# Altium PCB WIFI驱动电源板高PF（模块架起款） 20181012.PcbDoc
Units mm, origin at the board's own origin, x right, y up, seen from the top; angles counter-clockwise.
Board outline 211.1 x 130.13 mm, 2 copper layers (Top Layer, Bottom Layer); 46 components, 31 nets, 127 pads, 47 vias.
Unrouted connection lines stored in the file: 10.
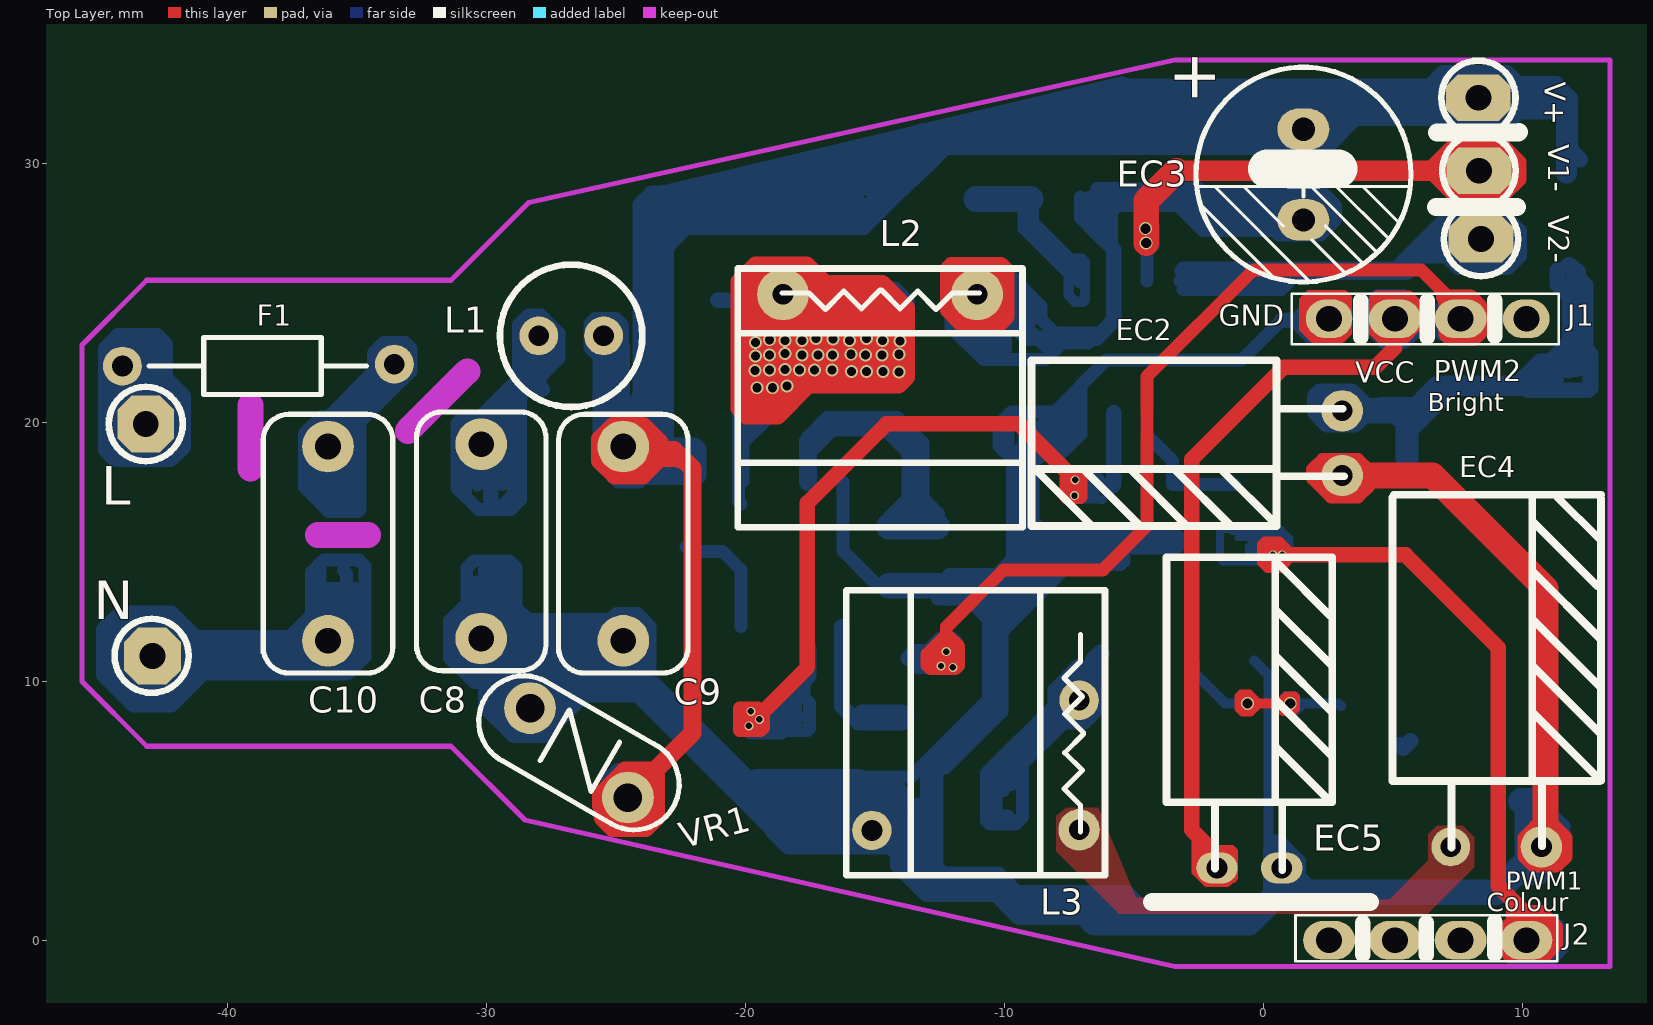
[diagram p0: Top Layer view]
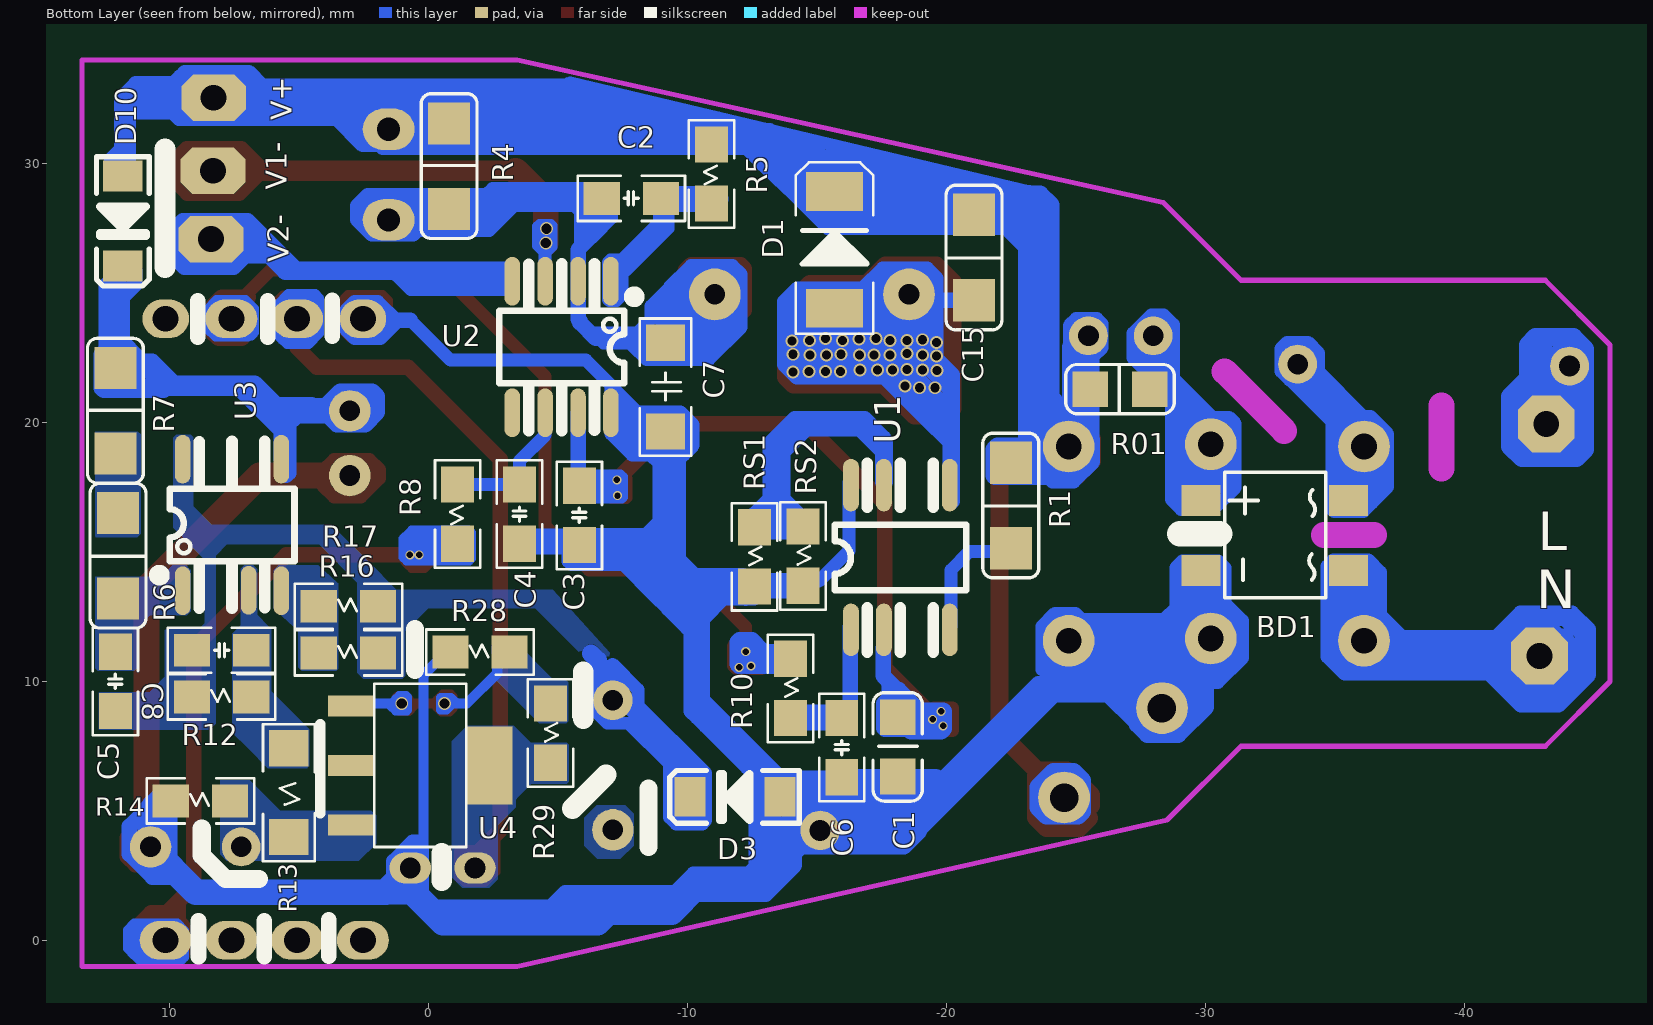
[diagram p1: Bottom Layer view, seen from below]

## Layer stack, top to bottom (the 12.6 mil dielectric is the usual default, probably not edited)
Top Solder: solder mask 0.0102, Solder Resist, Dk 3.5
Top Layer: signal copper 0.0356
Dielectric1: dielectric 0.32, FR-4, Dk 4.8
Bottom Layer: signal copper 0.0356
Bottom Solder: solder mask 0.0102, Solder Resist, Dk 3.5

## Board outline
-115.3,59.225 45.25,59.225 47.95,56.525 58.1,46.375 58.1,-51.3 38.5,-70.9 -67.65,-70.9 -123.775,-70.9 -153,-41.675 -153,21.525 -115.3,59.225

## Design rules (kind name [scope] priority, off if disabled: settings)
Clearance [All vs OnLayer('Keep-Out Layer')] p1: gap=0.4 ignorepadtopadclearanceinfootprint=FALSE except(0: Arc-Hole Track-Hole SMDPad-Hole THPad-Hole Via-Hole Fill-Hole Poly-Hole Region-Hole Text-Hole)
FabricationTestpoint [(IsPad And (OnTopLayer Or OnBottomLayer))] p1: side=3 testpointundercomponent=TRUE minsize=1.016 maxsize=2.54 preferedsize=1.524 minholesize=0 maxholesize=1.016 preferedholesize=0.813 testpointgrid=0.025 allowsidetop=TRUE allowsidebottom=TRUE usegrid=TRUE gridtolerance=0
PolygonConnect [All] p1: connectstyle=Direct reliefconductorwidth=0.254 reliefentries=4 polygonreliefangle="90 Angle" airgapwidth=0.254
RoutingVias [All] p1: holewidth=0.711 width=1.27 viastyle="Through Hole" minholewidth=0.2 minwidth=0.2 maxholewidth=1 maxwidth=1.27
SilkToSolderMaskClearance SilkscreenOverComponentPads [IsPad] p1: minsilkscreentomaskgap=0.254 clearancetoexposedcopper=TRUE
SolderMaskExpansion [All] p1: expansion=0.102
Width [All] p1: maxlimit=1 minlimit=0.2 preferedwidth=0.254 minimp=50.000000 maximp=50.000000 favimp=50.000000
28 further rules are at their usual default settings.

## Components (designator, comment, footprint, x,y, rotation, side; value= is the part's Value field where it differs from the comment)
BD1 "Comment" BD1 -31.877,15.824 r0 top
C1 "51K" C0805 -18.11,8.611 r0 bottom
C2 "Comment" C/0805(B)-new -7.823,28.651 r270 bottom
C3 "Comment" C/0805(B)-new -5.817,16.408 r0 bottom
C4 "Comment" C/0805(B)-new -3.505,16.459 r0 bottom
C5 "" C/0805(B)-new 12.1,10 r180 bottom (schematic designator C3)
C6 "Comment" C/0805(B)-new -15.951,7.442 r0 bottom
C7 "Comment" C/1206(B)-new -9.144,21.361 r180 bottom
C8 "Comment" CBB7.5-10*5 -30.201,15.405 r270 top
C8 "" C/0805(B)-new 8,11.2 r90 bottom (schematic designator C3)
C9 "Comment" CBB7.5-10*5 -24.714,15.316 r270 top
C10 "Comment" CBB7.5-10*5 -36.119,15.316 r270 top
C15 "0R82" R1206 -21.057,24.714 r180 bottom
D1 "ES3J" SMA-A -15.672,24.409 r270 bottom
D3 "ES1J" SOD123 -13.564,5.537 r90 bottom (schematic designator D5)
D10 "Comment" SOD123 11.811,29.515 r0 bottom
EC2 "Comment" CE6.3*10*2.5#1 3.048,19.197 r270 top
EC3 "+" CE3.5-D8.0 1.549,31.318 r90 top
EC4 "Comment" CE8*11*3.5 8.992,3.607 r0 top
EC5 "47uF/35V" CE6.3*10*2.5#2 -0.539,2.794 r0 top (schematic designator CE2)
F1 "Comment" R1/2W-H8 -35.179,22.174 r180 top
L1 "1.5mH" L5*7 -27.976,23.343 r270 top
L2 "Comment" TR-EE10E#1 -11.049,24.943 r270 top
L3 "Comment" TR-EE10E#2 -7.112,4.267 r180 top
R01 "0R82" R0805 -25.552,21.285 r270 bottom
R1 "0R82" R1206 -22.479,15.138 r180 bottom
R4 "0R82" R1206 -0.787,31.547 r0 bottom
R5 "Comment" R/0805(B)-NEW -10.922,29.591 r0 bottom
R6 "0R82" R1206 12,13.2 r180 bottom
R7 "0R82" R1206 12.1,22.1 r0 bottom
R8 "Comment" R/0805(B)-NEW -1.118,16.459 r0 bottom
R10 "Comment" R/0805(B)-NEW -13.97,9.728 r180 bottom
R12 "R0603_22/5%" R/0805(B)-NEW 8,9.4 r90 bottom (schematic designator "R3 52.6K")
R13 "Comment" R/1206(B)-NEW 5.4,5.7 r180 bottom
R14 "R1" R/0805(B)-NEW 8.814,5.385 r90 bottom (schematic designator "R2 82.5K")
R16 "R0603_22/5%" R/0805(B)-NEW 3.1,11.1 r90 bottom (schematic designator "R3 52.6K")
R17 "R0603_22/5%" R/0805(B)-NEW 3.1,12.9 r90 bottom (schematic designator "R3 52.6K")
R28 "R0603_22/5%" R/0805(B)-NEW -1.981,11.125 r90 bottom (schematic designator "R3 52.6K")
R29 "R0603_22/5%" R/0805(B)-NEW -4.7,8 r180 bottom (schematic designator "R3 52.6K")
RS1 "0R82" R/0805(B)-NEW -12.578,14.809 r180 bottom
RS2 "0R82" R/0805(B)-NEW -14.453,14.834 r180 bottom
U1 "Comment" SO8-B -16.307,11.989 r90 bottom
U2 "Comment" SOP-8 -7.036,25.451 r0 bottom
U3 "Comment" SOP-7 9.5,13.5 r180 bottom
U4 "Comment" SOT-223 2.1,9.9 r270 bottom
VR1 "Comment" VR7D -28.317,8.964 r60 top

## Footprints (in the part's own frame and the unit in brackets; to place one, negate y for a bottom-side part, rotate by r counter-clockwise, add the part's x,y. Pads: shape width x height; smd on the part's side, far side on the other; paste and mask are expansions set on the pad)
BD1 [mm]
  rect 1.5x1.2 smd far side: 1(-3.648,-1.538) 2(2.052,1.162) 3(-3.648,1.162) 4(2.052,-1.538)
C0805 [mil]
  rect 54x54 smd: 1(0,0) 2(0,90)
  silkscreen extent -38,-38 38,128
C/0805(B)-new [mm]
  rect 1.27x1.4 smd: 1(0,1.143) 2(0,-1.143)
  silkscreen extent -0.88,-2.08 0.88,2.08
C/1206(B)-new [mil]
  rect 60x55.12 smd: 1(0,67.5) 2(0,-67.5)
  silkscreen extent -39,-104 39,104
CBB7.5-10*5 [mm]
  round 2 hole 1: 1(-3.75,0) 2(3.75,0)
  silkscreen extent -5,-2.5 5,2.5
CE3.5-D8.0 [mm]
  oval 1.6x2 hole 0.9: 1(0,0) 2(-3.5,0)
  silkscreen extent -5.9,-4.15 2.4,4.15
CE6.3*10*2.5#1 [mm]
  round 1.6 hole 0.8: 1(-1.25,0) 2(1.25,0)
  silkscreen extent -3.2,-12 3.2,0.07
CE6.3*10*2.5#2 [mm]
  oval 1.6x1.2 hole 0.8: 1(-1.25,0) 2(1.25,0)
  silkscreen extent -3.2,-0.07 3.2,12
CE8*11*3.5 [mm]
  round 1.5 hole 0.8: 1(-1.75,0)
  round 1.6 hole 0.8: 2(1.75,0)
  silkscreen extent -4,-0.02 4.05,13.6
L5*7 [mm]
  round 1.5 hole 0.8: 1(0,2.5) 2(0,0)
  silkscreen extent -2.75,-1.5 2.75,4
R1/2W-H8 [mm]
  round 1.5 hole 0.8: 1(-1.625,-0.075) 2(8.875,0)
  silkscreen extent -0.55,-1.1 7.85,1.1
R0805 [mil]
  rect 54x54 smd: 1(0,0) 2(0,90)
  silkscreen extent -38,-38 38,128
R1206 [mil]
  rect 64x64 smd: 1(0,0) 2(0,130)
  silkscreen extent -42,-45 43,175
R/0805(B)-NEW [mm]
  rect 1.27x1.4 smd: 1(0,1.143) 2(0,-1.143)
  silkscreen extent -0.88,-2.07 0.88,2.07
R/1206(B)-NEW [mil]
  rect 60x55.12 smd: 1(0,67.5) 2(0,-67.5)
  silkscreen extent -39,-104 39,104
SMA-A [mm]
  rect 1.5x2.2 smd: 1(0,0) 2(-4.5,0)
  silkscreen extent -5.63,-1.5 0.98,1.5
SO8-B [mil]
  oval 80x24 smd: 1DIM(0,0) 2VCC(0,-50) 4HV(0,-150) 5DRAIN(220,-150) 7CS(220,-50) 8GND(220,0)
  oval 80x24 on Bottom Overlay: 3(0,-100) 6(220,-100)
  silkscreen extent -34,-175 253,25
SOD123 [mil]
  rect 60x47.24 smd: 1(0,0) 2(0,137)
  silkscreen extent -40,-29 40,167
SOP-7 [mm]
  oval 0.6x1.88 smd: 1(0,0) 2(2.543,0.02) 4(3.81,0) 5(3.81,5.08) 8(0,5.08)
  silkscreen extent -1.1,-0.68 4.32,5.77
SOP-8 [mm]
  oval 0.6x1.88 smd: 1(0,0) 2(1.27,0) 3(2.54,0) 4(3.81,0) 5(3.81,5.08) 6(2.54,5.08) 7(1.27,5.08) 8(0,5.08)
  silkscreen extent -1.1,-0.68 4.32,5.77
SOT-223 [mm]
  rect 0.82x1.785 smd: 1(0.85,-0.893) 2(3.15,-0.893) 3(5.45,-0.893)
  rect 3x1.785 smd: 2(3.15,4.443)
  silkscreen extent 0,0 6.3,3.55
TR-EE10E#1 [mm]
  round 2 hole 0.8: 1(0,0) 2(0,-7.5)
  silkscreen extent -1,-9.25 9,1.75
TR-EE10E#2 [mm]
  round 1.6 hole 0.8: 1(0,0)
  round 1.6 on Top Overlay: 2(0,-7.5)
  silkscreen extent -1,-9.25 9,1.75
VR7D [mm]
  round 2 hole 1.1: 1(0,0) 2(-1.1,-5)
  silkscreen extent -2.3,-6.7 1.2,1.7

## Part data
C5 C8: library part Cap, "Capacitor"
D3: library part DIODE0
EC5: "Polarized Capacitor (Radial)"
R12 R14 R16 R17 R28 R29: library part "Res Semi", "Semiconductor Resistor"

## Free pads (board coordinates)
  oct 2.2x2.2 hole 1: 0(-43.155,19.939) 0(-42.901,10.973)
  oct 2.5x1.8 hole 1: 0(8.306,32.537) 1(8.331,29.718) 1(8.407,27.076)
  oval 2x1.5 hole 1: 2(2.54,0) 2(5.08,0) 2(5.08,24) 2(7.62,0) 2(7.62,24) 2(10.16,0)
  oval 1.8x1.5 hole 1: 2(2.54,24) 2(10.16,24)
  round 1.1 on Keep-Out: 4(-11.049,17.094)
  round 1.524 hole 0.8: 5(-7.112,9.267) 6(-15.113,4.242)

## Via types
v1: diameter 0.5, hole 0.35, Top Layer to Bottom Layer, 33 vias
v2: diameter 0.35, hole 0.25, Top Layer to Bottom Layer, 10 vias
v3: diameter 0.5, hole 0.4, Top Layer to Bottom Layer, 4 vias

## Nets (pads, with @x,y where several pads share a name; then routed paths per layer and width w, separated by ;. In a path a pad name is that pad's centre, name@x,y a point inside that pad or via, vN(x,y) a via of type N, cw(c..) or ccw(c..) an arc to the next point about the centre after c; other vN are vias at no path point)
1: R16.1 R17.1 U3.4
2: R6.2 R7.2
3: EC5.1 pad.2@5.08,24 R29.2 U4.2@-2.343,6.75 | length 26.8
  Top Layer w0.6: EC5.1@-1.5,3 -2.769,4.269 -2.769,18.567 0.787,22.123 4.318,22.123 5.08,22.885 pad.2@5.08,24
4: R28.2 R29.1 U4.1 | length 6.6
  Top Layer w0.4: v3(-0.61,9.144) v3(1.041,9.144)
  Bottom Layer w0.4: R28.2@-2.643,10.8 -2.643,10.314 -1.473,9.144 v3(-0.61,9.144) ; v3(1.041,9.144) 2.898,9.144 U4.1
GND1: BD1.4 C1.2 C3.1 C4.1 C6.1 C7.2 C8.2@-30.201,11.655 C9.2 D3.1 EC4.2 EC5.2 pad.2@2.54,24 pad.6 R14.1 R28.1 RS1.2 RS2.2 U1.8GND U2.8 VR1.1 | length 90.4
  Bottom Layer w0.4: C8.2@-29.853,11.655 C8.2@-29.825,11.683 ; RS1.2@-12.603,13.691 RS1.2 ; RS1.2@-12.044,13.691 -11.841,13.894 -9.296,13.894 ; -7.366,15.392 -8.865,13.894 -9.296,13.894 ; U2.8 -9.284,20.371 -9.296,20.383 -9.296,13.894 ; C4.1@-3.429,15.392 C4.1@-3.378,15.443 ; R28.1@-0.357,10.8 0.203,10.24 EC5.2@0.203,3.124 ; pad.2@2.588,23.952 pad.2@2.858,23.682
  Bottom Layer w0.5: U1.8GND@-16.231,17.704 -16.231,15.037 RS2.2@-15.062,13.868 ; U2.8 -7.036,21.438 -6.071,22.403 -0.838,22.403 0.711,23.952
  Bottom Layer w0.6: 0.711,23.952 pad.2@2.588,23.952
  Bottom Layer w1: C8.2@-29.853,11.655 -24.803,11.655 C9.2 C9.2@-24.714,11.278 ; C8.2@-29.825,11.683 BD1.4 ; -19.558,6.121 -15.951,6.121 -15.646,6.121 -13.856,4.331 -13.856,3.505 ; RS2.2 RS1.2@-12.603,13.691 ; -13.716,3.505 -13.716,3.073 -12.7,2.057 -10.338,2.057 -9.37,1.09 -6.92,1.09 -6.516,0.686 -0.559,0.686 0.711,1.956 EC5.2 1.651,1.854 8.989,1.854 EC4.2 10.742,4.981 10.338,5.385 R14.1 ; -7.366,15.392 C4.1@-3.429,15.392
NetB1_2: 
NetC3_1: C5.1 R6.1 U3.1
NetC3_2: C5.2 C8.1@9.143,11.2 D3.2 pad.5 R12.1 R16.2 R17.2 U3.8
NetCE2_1: EC4.1 L3.1 R13.2 R14.2 U4.3
"NetR2 82.5K_2": C8.2@6.857,11.2 R12.2 R13.1 U3.2 | length 0.6
  Bottom Layer w0.6: R13.1@5.257,7.557 R13.1 R13.1@5.685,7.7
NewNet1: RS1.1 RS2.1 U1.7CS | length 10.8
  Bottom Layer w0.4: RS1.1@-12.603,15.977 RS1.1
  Bottom Layer w0.7: U1.7CS@-17.577,17.704 -17.577,18.898 -16.434,20.041 -14.376,20.041 -13.614,19.279 -13.614,16.307
  Bottom Layer w1: RS2.1 RS1.1@-12.603,15.977
NewNet2: 
NewNet3: R1.1 U1.4HV | length 4.7
  Bottom Layer w0.5: R1.1@-22.301,15.215 -22.098,15.011 -20.879,15.011 -20.168,14.3 U1.4HV@-20.168,12.116
NewNet4: C1.1 C3.2 U1.2VCC U2.7 | length 32.6
  Top Layer w0.6: v2(-19.863,8.28) -17.602,10.541 -17.602,16.891 -14.554,19.939 -9.423,19.939 -7.29,17.805 v2(-7.29,17.17)
  Bottom Layer w0.6: v2(-19.863,8.28) -19.736,8.407 -18.11,8.407 C1.1 -18.11,9.652 -17.551,10.211 U1.2VCC@-17.551,11.303 ; v2(-7.29,17.17) -7.264,17.196 v2(-7.264,17.78) -7.036,17.551 C3.2 -5.766,17.602 U2.7
  other v2: -19.456,8.534 -19.787,8.839
NewNet5: C9.1 C15.2 D1.2 EC2.1 EC3.1 L1.1 pad.0@8.306,32.537 R01.1 R1.2 R4.1 R5.2 R7.1 U3.5 VR1.2 | length 78.8
  Bottom Layer w0.5: R01.1 -25.476,21.361 L1.1 -25.121,23.343 -24.714,22.936 C9.1 ; -23.825,27.889 -23.194,28.913 -11.166,31.763 -5.466,33.114 -4.902,32.766 ; R1.2@-22.301,18.517 -22.851,19.066 C9.1 ; D1.2@-15.646,28.626 -20.117,28.626 -20.904,27.838 -22.758,27.838 -23.393,27.203 -23.393,20.387 C9.1 ; -13.36,30.378 -12.85,30.889 -11.002,30.889 -10.21,31.681 ; EC3.1@1.187,31.681 EC3.1 ; R7.1 R7.1@12.636,22.636
  Bottom Layer w0.6: U3.5 5.69,19.736
  Bottom Layer w0.7: 5.69,19.736 7.315,21.361 10.109,21.361 10.848,22.1 R7.1
  Bottom Layer w1: -10.21,31.681 EC3.1@1.187,31.681 ; EC3.1 2.769,32.537 pad.0@8.306,32.537
NewNet6: C2.2 C7.1 EC3.2 L2.1 R4.2 U2.2 | length 20.7
  Bottom Layer w0.6: L2.1@-11.227,25.349 -9.119,23.241 -6.452,23.241 -5.842,23.851 -5.842,23.901 -5.766,23.978 U2.2 -5.766,26.67 -6.68,27.584 C2.2 -3.15,28.651 -2.642,28.143 ; EC3.2@1.224,28.143 EC3.2 EC3.2@1.824,28.092
  Bottom Layer w0.8: -2.642,28.143 EC3.2@1.224,28.143
NewNet7: D1.1 L2.2 U1.5DRAIN | length 11.4
  Bottom Layer w0.4: U1.5DRAIN@-20.041,17.704 -20.041,21.234 -17.662,23.613 -16.612,23.613 -16.3,23.613 -18.214,25.527 L2.2@-18.676,25.527
  other v1: -19.558,21.336 -18.948,21.336 -18.39,21.412 -14.072,21.946 -15.9,21.971 -15.316,21.971 -14.681,21.971 -19.634,21.996 -19.075,22.022 -17.907,22.022 -17.323,22.022 -16.662,22.022 -18.466,22.047 -19.609,22.555 -19.075,22.606 -17.805,22.606 -17.196,22.606 -16.637,22.606 -15.367,22.606 -14.732,22.606 -15.926,22.631 -14.072,22.631 -18.466,22.657 -19.609,23.089 -14.021,23.139 -18.466,23.165 -17.805,23.165 -15.977,23.165 -14.707,23.165 -19.075,23.19 -16.612,23.216 -17.272,23.241 -15.316,23.241
NewNet8: 
NewNet9: 
NewNet10: BD1.3 C10.1 F1.1 | length 6
  Bottom Layer w1: C10.1 -36.119,17.64 BD1.3@-35.525,17.046
  Bottom Layer w1.5: C10.1@-36.17,19.447 F1.1@-33.51,22.107
NewNet11: BD1.1 pad.0@-42.901,10.973
NewNet12: BD1.2 C8.1@-30.201,19.155 L1.2 R01.2 | length 8.6
  Bottom Layer w0.6: BD1.2 -29.825,19.275 -30.201,19.65 -30.201,20.193 -27.976,22.417 ; L1.2 -27.976,22.417 ; R01.2 -27.976,21.423 -27.976,22.417
NewNet13: F1.2 pad.0@-43.155,19.939 | length 2.9
  Bottom Layer w1: F1.2@-43.741,22.567 -43.155,21.98 pad.0@-43.155,19.939
NewNet14: pad.2@7.62,24 R10.1 | length 32.6
  Top Layer w0.5: v2(-12.243,11.151) -12.243,12.09 -10.033,14.3 -6.198,14.3 -4.496,16.002 -4.496,21.768 -0.381,25.883 6.096,25.883 pad.2@7.62,24.359
  Top Layer w0.6: pad.2@7.546,23.926 7.62,24 pad.2@7.62,24.359
  Bottom Layer w0.6: R10.1@-13.716,10.897 -13.462,11.151 v2(-12.243,11.151)
NewNet15: pad.2@10.16,0 R8.1 | length 21.9
  Top Layer w0.6: v2(0.374,14.88) v2(0.73,14.88) 5.491,14.88 9.068,11.303 9.068,2.108 10.16,1.016 pad.2@10.16,0
NewNet16: C4.2 R8.2 U2.6 | length 5.6
  Bottom Layer w0.5: U2.6 -4.496,19.507 -3.505,18.517 C4.2 R8.2
NewNet17: C2.1 R5.1 U2.1 | length 6.1
  Bottom Layer w0.6: C2.1@-8.992,28.626 C2.1 -8.966,27.711 -7.036,25.781 U2.1
  Bottom Layer w1: R5.1@-11.074,28.626 C2.1@-8.992,28.626
NewNet18: pad.1@8.331,29.718 U2.3 | length 16.4
  Top Layer w0.8: -3.353,29.718 pad.1@8.331,29.718
  Top Layer w1: v3(-4.521,26.924) -4.521,28.55 -3.353,29.718
  Bottom Layer w0.5: v3(-4.521,26.924) -4.496,26.899 U2.3
  other v3: -4.547,27.483
NewNet19: pad.1@8.407,27.076 U2.4 | length 11
  Bottom Layer w0.7: U2.4@-3.073,25.857 5.537,25.857 6.731,27.051 pad.1@7.391,27.051
PWM1: C6.2 R10.2 U1.1DIM | length 5.7
  Bottom Layer w0.6: U1.1DIM@-16.281,12.116 -16.281,9.042 -15.646,8.407 C6.2@-15.443,8.611
  Bottom Layer w1: C6.2@-15.443,8.611 R10.2@-13.97,8.611
vcc: 
pads on no net: C10.2 C15.1 D10.1 D10.2 EC2.2 L3.2 U1.3 U1.6 U2.5 U4.2@2.992,6.75
copper on no net: | length 1192.8
  Top Layer w0.3: -2.413,3.531 -1.219,3.531 -1.118,3.429 ; -0.61,9.144 -0.864,9.398 -0.864,9.525 ; 0.559,9.017 0.762,8.814 1.143,8.814 1.27,8.941 1.27,9.398 1.219,9.449 0.864,9.449 0.737,9.322 0.737,9.246 ; 1.803,23.647 1.778,23.673 1.778,24.968 ; 3.099,24.613 2.997,24.714 1.524,24.714 ; 4.394,24.587 4.445,24.638 5.944,24.638 ; 10.742,3.607 10.897,3.762 ; -1.118,3.429 -1.168,3.378 -2.21,3.378 -2.388,3.2 -2.438,3.2 -2.564,3.326 -2.564,4.064 -2.616,4.012 -2.616,2.642 -2.184,2.21 -1.397,2.21 -1.245,2.362 -1.168,2.362 -1.118,2.413 -1.118,3.429 ; -0.864,9.525 -0.533,9.525 -0.305,9.296 -0.305,8.966 -0.483,8.788 -0.813,8.788 -0.965,8.941 -0.965,9.423 -0.864,9.525 ; -0.102,14.58 0.356,14.58 0.406,14.529 0.813,14.529 0.838,14.503 ; -0.102,14.58 0.051,14.732 0.051,15.062 0.178,15.189 0.66,15.189 0.559,15.291 -0.102,15.291 ; -0.102,14.58 -0.102,15.291 ; -0.102,14.58 0.152,14.326 0.66,14.326 0.838,14.503 ; -0.102,15.291 0.051,15.443 ; -0.102,15.291 0.051,15.443 ; 0.051,15.443 0.635,15.443 0.94,15.138 0.94,14.605 0.838,14.503 ; 1.524,24.714 1.524,23.622 1.93,23.216 3.023,23.216 3.277,23.47 3.277,24.816 3.124,24.968 1.778,24.968 ; 1.524,24.714 1.778,24.968 ; 4.242,24.79 4.242,23.47 4.445,23.266 4.496,23.216 5.512,23.216 5.944,23.647 5.944,24.638 ; 4.242,24.79 4.394,24.943 5.639,24.943 5.944,24.638 ; 4.242,24.79 5.791,24.79 5.944,24.638 ; -7.722,17.069 -7.722,17.831 -7.518,18.034 -7.01,18.034 -6.934,17.958 -6.934,17.094 -7.036,16.993 -7.645,16.993 -7.722,17.069
  Top Layer w0.5: -19.456,8.534 -19.888,8.966 -20.218,8.966 ; -12.243,11.151 -12.624,10.77 -12.649,10.77 -12.624,10.795 -12.09,10.795 -12.243,10.947 -12.243,11.786 ; 2.362,17.755 2.286,17.831 2.286,18.567 ; -20.218,8.966 -20.218,8.103 -19.406,8.103 -19.304,8.204 -19.304,8.763 -19.507,8.966 -20.218,8.966 ; -12.243,11.786 -12.979,11.049 -12.979,10.617 -12.852,10.49 -11.887,10.49 -11.76,10.617 -11.76,11.354 -12.192,11.786 -12.243,11.786 ; 2.286,18.567 1.905,18.186 1.905,17.831 2.616,17.12 3.658,17.12 4.089,17.551 4.089,18.136 3.658,18.567 2.286,18.567
  Top Layer w0.6: -20.091,25.07 -14.656,25.07 -14.605,25.121 ; -20.066,21.209 -17.805,21.209 -17.602,21.412 ; -20.015,8.661 -19.914,8.661 -19.837,8.585 ; -19.99,25.629 -17.831,25.629 -17.399,25.197 ; -18.847,20.828 -18.974,20.701 -19.914,20.701 -19.71,20.498 -18.847,20.498 -17.932,21.412 -17.602,21.412 ; -17.577,21.387 -18.745,20.218 -19.964,20.218 -20.269,20.523 -20.269,25.451 -19.609,26.111 -17.628,26.111 -16.916,25.4 -14.707,25.4 -13.741,24.435 -13.741,21.742 -14.072,21.412 -17.602,21.412 ; -14.249,21.666 -13.995,21.92 -13.995,24.638 ; -12.014,25.375 -11.963,25.375 -11.633,25.705 -10.338,24.409 -10.338,24.181 -10.312,24.206 -10.312,25.654 -10.744,26.086 -12.04,26.086 ; 6.198,29.743 6.426,29.743 ; 10.871,4.801 10.871,4.699 10.109,3.937 10.109,3.251 10.439,2.921 11.328,2.921 11.633,3.226 11.633,3.962 11.074,4.521 ; -12.04,26.086 -12.192,25.933 -12.192,24.333 -11.684,23.825 -10.16,23.825 -9.906,24.079 -9.906,25.857 -10.135,26.086 -12.04,26.086 ; 6.426,29.743 7.315,28.854 9.322,28.854 9.855,29.388 9.855,30.048 9.347,30.556 7.239,30.556 6.426,29.743
  Top Layer w0.7: -25.578,5.207 -25.578,5.613 -24.638,6.553 -23.647,6.553 -23.444,6.35 -23.444,4.75 -23.851,4.343 -25.121,4.343 -25.502,4.724 ; -24.536,5.512 -22.047,8.001 -22.047,10.211 -22.047,18.212 -22.758,18.923 -24.359,18.923 ; -22.53,18.567 -22.581,18.618 -23.317,18.618 ; 7.01,24.841 7.112,24.74 7.112,23.419 7.239,23.292 8.103,23.292 8.306,23.495 8.306,24.46 7.976,24.79 7.264,24.79 ; 9.728,1.346 9.728,0.711 9.55,0.533 9.55,-0.508 10.846,-0.508 11.227,-0.127 11.227,0.483 10.693,1.016 10.16,1.016 ; -23.317,18.618 -23.978,17.958 -25.044,17.958 -25.603,18.517 -25.603,19.355 -25.095,19.863 -23.952,19.863 -23.317,19.228 -23.317,18.618
  Top Layer w1: 3.048,17.947 6.539,17.947 10.897,13.589 10.897,10.033 10.897,3.762
  Bottom Layer w0.3: -20.168,20.803 -20.168,21.59 -19.482,22.276 ; -19.736,24.714 -19.71,24.689 ; -8.179,23.546 -6.274,23.546 -6.147,23.673 ; -7.874,22.962 -6.731,22.962 -6.452,23.241 ; -7.01,17.17 -6.985,17.196 -6.502,17.196 -6.299,16.993 -6.198,16.993 -6.223,17.018 -7.468,17.018 -7.544,17.094 -7.544,17.907 -7.417,18.034 -7.29,18.034 ; -5.766,26.67 -5.766,28.219 -5.613,28.372 ; -1.194,15.799 0.737,15.799 ; -1.067,9.22 -1.041,9.22 ; -0.965,15.57 0.965,15.57 1.016,15.519 ; 1.321,9.271 1.321,9.296 1.143,9.474 0.864,9.474 0.787,9.398 0.787,8.89 0.838,8.839 1.295,8.839 1.473,9.017 ; 4.369,24.562 4.394,24.587 5.563,24.587 5.334,24.816 4.191,24.816 ; 4.496,23.241 4.572,23.165 5.664,23.165 ; -7.29,18.034 -7.137,17.882 -6.858,17.882 -6.807,17.831 -6.274,17.831 -6.477,18.034 -7.29,18.034 ; -4.724,27.711 -4.496,27.483 -4.496,27.127 ; -4.724,27.711 -4.826,27.61 -4.826,26.772 -4.648,26.594 -4.343,26.594 -4.14,26.797 -4.14,27.584 -4.267,27.711 ; -4.724,27.711 -4.267,27.711 ; -4.496,27.127 -4.267,27.356 -4.267,27.711 ; -4.496,27.127 -4.648,27.28 -4.648,27.33 -4.267,27.711 ; -4.496,27.127 -4.496,26.899 -4.267,27.127 -4.267,27.711 ; -1.041,9.22 -0.864,9.398 -0.457,9.398 -0.432,9.373 -0.432,8.89 -0.457,8.865 -0.686,8.865 -1.041,9.22 ; -0.559,15.189 -0.249,14.88 ; -0.559,15.189 -0.249,14.88 ; -0.559,15.189 -0.406,15.342 0.762,15.342 0.787,15.316 ; -0.559,15.189 -0.559,14.91 -0.529,14.88 0.73,14.88 ; -0.249,14.88 -0.249,15.143 -0.229,15.164 0.635,15.164 0.787,15.316 ; -0.249,14.88 0.73,14.88 ; 0.73,14.88 0.787,14.938 0.787,15.316 ; 0.73,14.88 1.016,15.166 1.016,15.519 ; 0.737,15.799 0.66,15.875 -1.549,15.875 -1.676,15.748 -1.676,14.732 -1.575,14.63 0.864,14.63 1.016,14.783 1.016,15.519 ; 0.737,15.799 1.016,15.519 ; 4.191,23.419 4.623,22.987 5.486,22.987 5.664,23.165 ; 4.191,23.419 4.191,24.816 ; 4.191,23.419 4.699,23.419 4.978,23.139 5.639,23.139 5.664,23.165 ; 4.191,24.816 4.369,24.994 ; 4.191,24.816 4.369,24.994 ; 4.369,24.994 5.436,24.994 5.893,24.536 5.893,23.368 5.69,23.165 5.664,23.165 ; 9.703,0.686 11.379,0.686 11.659,0.406 11.659,-0.33 ; 9.703,0.686 9.398,0.381 9.398,-0.66 9.525,-0.787 11.201,-0.787 11.659,-0.33 ; 9.703,0.686 10.998,0.686 ; 10.998,0.686 11.481,0.203 11.481,-0.051 ; 10.998,0.686 10.998,0.254 11.303,-0.051 ; 11.303,-0.051 11.481,-0.051 ; 11.303,-0.051 11.024,-0.33 11.024,-0.508 10.922,-0.61 11.379,-0.61 ; 11.303,-0.051 11.303,-0.533 11.379,-0.61 ; 11.379,-0.61 11.659,-0.33 ; 11.379,-0.61 11.481,-0.508 11.481,-0.051 ; 11.481,-0.051 10.897,-0.635 10.897,0.203 11.024,0.33 11.1,0.33 11.481,-0.051 ; 11.481,-0.051 11.659,-0.229 11.659,-0.33
  Bottom Layer w0.4: -22.657,27.432 -15.392,27.432 -12.751,30.074 ; -9.296,28.169 -9.296,27.483 -7.62,25.806 ; -7.569,26.441 -7.442,26.314 -7.01,26.314 -6.883,26.187 -6.883,24.74 -6.96,24.663 -7.264,24.663 -7.518,24.917 -7.518,26.187 ; 6.756,23.47 6.858,23.368 6.934,23.368 6.985,23.317 8.23,23.317 8.534,23.622 8.534,24.359 8.179,24.714 7.087,24.714 6.756,24.384 6.756,23.47
  Bottom Layer w0.5: -42.901,10.973 -36.712,10.973 -36.119,11.566 -36.119,11.862 -35.408,12.573 -35.408,14.168 -35.525,14.286 ; -36.601,18.593 -36.83,18.364 -36.83,17.805 -36.424,17.399 -36.424,17.17 ; -36.424,14.3 -36.424,12.598 -36.398,12.573 ; -36.22,13.589 -35.077,13.589 -35.001,13.513 -35.001,11.125 -35.509,10.617 ; -36.17,12.827 -35.865,12.522 -35.865,12.497 -35.687,12.675 -35.687,13.31 -35.738,13.259 -36.144,13.259 -35.966,13.081 -35.763,13.081 -35.306,12.624 -35.306,12.192 -35.509,11.989 -35.509,10.617 ; -35.585,20.218 -36.373,20.218 -37.033,19.558 -37.033,17.501 -36.424,16.891 -36.093,16.561 -34.95,16.561 -34.874,16.637 -34.874,19.914 ; -35.484,18.644 -35.56,18.567 -35.56,17.932 -35.204,17.577 -35.154,17.628 -35.154,19.533 ; -34.366,21.971 -34.366,22.682 -33.96,23.089 -33.147,23.089 -32.918,22.86 -32.918,21.971 -33.249,21.641 ; -30.81,17.323 -30.81,18.567 -30.709,18.669 -30.709,18.44 -30.277,18.009 -30.277,17.653 -30.353,17.577 -30.353,17.678 -30.607,17.932 ; -29.82,19.609 -29.82,20.041 -29.337,20.523 ; -29.388,17.602 -29.337,17.653 -29.337,20.523 ; -28.448,22.327 -28.448,22.885 -28.296,23.038 -28.296,22.737 -27.976,22.417 -27.407,22.987 -27.407,22.631 -27.635,22.403 ; -25.502,20.015 -25.4,20.117 -25.4,22.2 -25.375,22.174 -25.375,20.498 -24.968,20.091 -24.968,20.066 ; -25.476,22.53 -25.654,22.53 ; -24.994,9.931 -24.663,9.931 -18.999,4.267 -18.999,4.191 -18.364,3.556 -14.199,3.556 -13.716,3.073 ; -24.206,11.557 -24.206,10.566 -23.952,10.312 -23.952,11.125 -23.851,11.227 ; -23.825,27.889 -23.825,20.472 -24.232,20.066 ; -23.673,10.465 -23.673,12.116 -24.181,12.624 -24.968,12.624 -25.197,12.395 -28.397,12.395 -28.854,12.852 -28.854,14.402 -29.108,14.656 -30.302,14.656 -30.48,14.656 -30.759,14.376 -30.759,13.005 -31.42,12.344 -31.42,10.897 -30.48,9.957 -23.52,9.957 -19.126,5.563 -16.403,5.563 -14.615,3.775 ; -22.403,27.356 -23.012,26.746 -23.012,18.771 -24.079,17.704 -24.917,17.704 -25.679,18.466 -25.679,19.355 ; -20.168,16.84 -20.269,16.942 -20.269,21.844 -19.634,22.479 -19.634,25.578 -19.253,25.959 -17.526,25.959 -16.764,25.197 -14.224,25.197 -13.691,24.663 -13.691,22.225 -14.199,21.717 -17.577,21.717 -19.152,20.142 -20.091,19.202 -20.091,18.364 ; -19.914,6.198 -19.228,5.512 -17.45,5.512 ; -19.863,8.814 -18.263,8.814 -19.761,8.814 -19.787,8.839 -19.863,8.839 ; -19.787,8.103 -17.602,8.103 -17.526,8.179 -17.526,9.169 -17.729,9.373 -17.729,9.931 -17.704,9.957 ; -17.678,18.593 -17.678,19.304 -17.602,19.38 -17.602,19.431 -16.84,20.193 -14.122,20.193 -13.411,19.482 -13.132,19.202 -13.132,16.51 -12.929,16.307 ; -16.764,19.71 -14.605,19.71 -13.716,18.821 ; -15.951,6.299 -13.614,6.299 -11.1,8.814 -10.617,9.296 -10.617,12.395 -11.405,13.183 -11.887,13.183 ; -15.088,27.864 -12.751,30.074 -11.76,31.064 0.254,31.064 0.635,30.683 2.565,30.683 3.581,31.699 9.652,31.699 10.084,32.131 10.084,32.918 9.627,33.376 9.601,33.376 9.423,33.553 6.934,33.553 6.401,33.02 -5.232,33.02 -6.934,31.318 -13.183,31.318 ; -14.427,16.358 -13.589,17.196 -13.259,17.196 ; -13.818,30.404 -12.903,31.318 -10.947,31.318 -10.389,31.877 ; -13.36,3.632 -13.36,5.258 ; -13.259,17.551 -13.259,17.196 ; -12.954,11.227 -12.929,11.227 -12.497,11.659 -11.989,11.659 -11.862,11.532 -11.862,10.643 -11.963,10.541 -13.36,10.541 -13.716,10.897 -12.09,10.897 -12.04,10.947 ; -12.649,2.692 -12.598,2.743 -12.598,6.96 ; -12.624,6.655 -12.268,6.655 -10.668,8.255 -10.338,8.585 ; -12.573,13.183 -10.795,13.183 -10.414,12.802 -10.414,9.144 -13.002,6.556 -13.002,3.248 -12.344,2.591 -10.211,2.591 -9.5,1.88 -5.258,1.88 -4.699,1.321 ; -12.548,16.485 -13.259,17.196 ; -12.243,13.157 -12.192,13.208 -12.192,14.072 -12.141,14.122 -10.287,14.122 -9.677,14.732 -9.677,18.567 ; -11.862,23.952 -11.862,23.927 -10.49,22.555 -10.236,22.555 ; -11.862,24.435 -11.862,24.181 -10.236,22.555 ; -11.405,24.206 -10.211,23.012 -10.211,22.962 -10.236,22.936 -10.236,22.555 ; -10.846,24.282 -10.135,23.571 -10.033,23.571 -9.957,23.495 -9.957,22.835 -10.236,22.555 ; -10.795,25.933 -10.617,25.933 -8.865,24.181 -8.865,24.028 -9.296,23.597 -9.525,23.597 -11.684,25.756 -11.151,25.756 -9.322,23.927 -9.322,24.181 -9.881,24.74 -9.881,24.409 -8.357,22.885 ; -10.516,13.386 -10.135,13.386 -9.83,13.691 ; -10.084,12.065 -10.084,8.839 -10.338,8.585 ; -10.033,5.791 -10.033,6.655 -8.534,8.153 -7.366,9.322 -7.167,9.322 -7.112,9.267 -7.112,10.287 ; -9.855,13.056 -9.83,13.081 -9.83,13.691 ; -9.855,19.863 -9.855,18.745 ; -9.652,13.31 -9.652,12.725 -9.296,13.081 -9.296,13.894 -9.957,13.233 -9.957,12.04 -9.22,12.776 -9.22,12.802 -8.712,13.31 -7.518,14.503 -5.512,14.503 -5.385,14.63 -5.385,15.596 -5.715,15.265 -5.817,15.265 -6.223,15.672 -8.382,15.672 -8.89,16.18 -8.89,18.415 -8.56,18.745 -7.849,18.745 -7.036,19.558 -7.036,20.98 ; -9.525,7.01 -9.525,6.223 -9.728,6.02 -10.008,6.02 -10.312,6.325 -10.312,4.928 -10.439,4.801 -9.855,4.801 -9.55,4.496 ; -9.271,19.075 -9.601,18.745 -9.855,18.745 ; -9.144,16.078 -9.144,15.977 -8.433,15.265 -6.604,15.265 -6.147,14.808 -7.645,14.808 -9.169,13.284 -9.169,15.57 -9.017,15.723 -8.077,14.783 -8.255,14.783 ; -8.661,14.58 -9.246,14.58 -10.033,13.792 -11.943,13.792 -12.044,13.691 -9.83,13.691 ; -8.001,19.634 -7.62,20.015 -7.62,20.396 ; -7.391,9.728 -7.112,10.008 -7.112,10.287 ; -7.061,28.702 -7.061,27.889 -6.502,27.33 ; -7.036,21.438 -7.036,21.412 -8.052,20.396 ; -6.807,10.592 -7.112,10.287 ; -6.627,10.772 -6.627,9.7 -6.35,9.423 -6.35,8.941 -6.909,8.382 -7.722,8.382 -9.296,6.807 -9.296,4.75 -9.55,4.496 ; -6.426,29.032 -2.464,29.032 -2.235,28.804 2.362,28.804 2.794,28.372 2.794,27.813 2.21,27.229 0.584,27.229 0.406,27.407 -2.337,27.407 -3.556,28.626 ; -6.274,28.727 -6.274,27.178 -6.223,27.127 ; -6.121,28.372 -3.226,28.372 -3.073,28.219 ; -6.071,1.321 -0.152,1.321 0.051,1.524 ; -5.766,26.67 -6.045,26.949 -6.045,27.94 -5.613,28.372 -5.334,28.372 ; -3.226,25.451 0.559,25.451 ; -3.099,25.121 0.686,25.121 1.016,25.451 ; -2.87,28.829 -2.616,28.829 -2.286,28.499 2.184,28.499 2.362,28.321 2.362,27.813 ; -2.311,27.661 0.813,27.661 0.864,27.711 ; 0.914,25.806 0.559,25.451 ; 1.422,25.857 1.016,25.451 ; 2.213,23.673 2.54,24 ; 4.928,25.908 5.055,25.908 6.985,27.838 9.5,27.838 ; 5.359,20.295 5.359,18.034 5.486,17.907 ; 6.121,26.365 6.147,26.391 7.061,26.391 7.518,25.933 9.449,25.933 9.931,26.416 9.931,27.407 9.5,27.838 ; 6.782,26.721 7.137,26.721 7.468,26.391 9.373,26.391 9.576,26.594 9.576,27.762 9.5,27.838 ; 6.909,27.483 7.315,27.483 7.341,27.457 ; 11.709,29.616 11.811,29.515 ; 11.887,22.428 12.065,22.606 ; -35.509,10.617 -41.25,10.617 -41.504,10.363 -42.443,9.423 -43.459,9.423 -44.501,10.465 -44.501,11.811 -44.272,12.04 -44.196,12.04 -43.84,12.395 -42.189,12.395 -42.164,12.37 -42.164,12.268 -41.427,11.532 -41.427,10.77 -41.834,10.363 -41.91,10.363 -42.545,9.728 -43.307,9.728 -43.993,10.414 -43.993,11.608 -43.815,11.786 -43.663,11.786 -43.409,12.04 -42.52,12.04 -42.443,12.116 -42.443,12.09 -41.707,11.354 -37.49,11.354 -36.932,11.913 -36.932,11.354 -37.084,11.201 -36.093,11.201 -35.509,10.617 ; -30.302,16.637 -29.515,16.637 -29.261,16.891 -29.261,16.916 -28.956,17.221 -28.956,20.955 -28.931,20.98 -28.931,20.93 -29.337,20.523 ; -30.302,16.637 -31.14,17.475 -31.14,19.964 -30.912,20.193 -30.201,20.193 -28.753,21.641 -28.753,23.774 -28.372,24.155 -27.915,24.155 -27.203,23.444 -27.203,22.479 -28.677,21.006 -28.677,17.018 -29.058,16.637 -30.302,16.637 ; -25.679,19.355 -25.654,19.38 ; -25.679,19.355 -25.654,19.38 ; -25.679,19.355 -24.968,20.066 ; -25.654,19.38 -25.654,22.123 -25.07,22.708 -25.07,20.168 -24.968,20.066 ; -25.654,19.38 -25.654,22.53 ; -25.654,22.53 -26.01,22.885 -26.01,23.8 -25.806,24.003 -24.994,24.003 -24.74,23.749 -24.74,20.574 -24.232,20.066 ; -24.968,20.066 -24.232,20.066 ; -10.338,8.585 -10.338,10.211 -10.109,10.439 -10.109,13.411 -9.83,13.691 ; -9.855,18.745 -9.677,18.567 ; -9.677,18.567 -9.093,18.567 -8.56,19.101 -8.56,19.888 -8.052,20.396 ; -9.677,18.567 -10.211,19.101 -10.211,19.914 -9.728,20.396 -8.052,20.396 ; -9.55,4.496 -10.566,4.496 -10.693,4.623 -10.693,6.452 -8.077,9.068 -8.077,9.682 -7.102,10.657 -7.102,10.297 -7.112,10.287 ; -8.255,14.783 -8.661,15.189 -8.839,15.189 -8.839,14.199 -8.255,14.783 ; -8.052,20.396 -7.62,20.396 ; -7.62,20.396 -8.103,19.914 -8.103,19.888 -8.28,19.71 -8.28,18.898 -7.544,19.634 -7.417,19.634 -7.264,19.787 -7.264,20.752 -7.62,20.396 ; 0.559,25.451 1.016,25.451 ; -44.831,10.236 -44.831,12.014 -44.171,12.675 -42.139,12.675 -41.199,11.735 -37.592,11.735 -36.754,12.573 -36.754,14.224 -36.297,14.681 -35.966,14.681 -34.925,14.681 -34.696,14.453 -34.696,10.947 -35.357,10.287 -40.919,10.287 -42.164,9.042 -43.637,9.042 -44.831,10.236 ; -12.065,23.673 -12.065,25.73 -11.735,26.06 -10.135,26.06 -9.271,25.197 -9.271,25.171 -8.585,24.486 -8.585,23.978 -7.874,23.266 -7.874,22.962 -8.407,22.428 -10.82,22.428 -12.065,23.673 ; 1.219,23.876 1.854,23.241 2.87,23.241 3.2,23.571 3.2,24.333 2.87,24.663 1.956,24.663 1.219,23.927 1.219,23.876
  Bottom Layer w0.6: -30.353,12.294 -30.353,11.303 -29.947,10.897 ; -30.201,19.05 -29.794,19.05 ; -23.444,19.837 -25.07,18.212 -25.07,18.186 -25.044,18.212 -24.003,18.212 -24.105,18.11 -24.587,18.11 -24.181,18.517 -23.851,18.517 -23.165,19.202 -23.165,20.726 ; -21.057,24.714 -19.736,24.714 ; -18.263,22.022 -14.3,22.022 -14.046,22.276 ; -17.653,5.563 -14.351,5.563 -13.97,5.182 -13.97,5.715 -14.224,5.969 -14.834,5.969 -14.859,5.994 ; -15.494,5.461 -15.494,5.004 -14.453,3.962 ; -15.316,4.775 -15.316,4.547 -13.614,2.845 ; -14.122,3.505 -14.122,2.896 -13.005,1.778 -9.652,1.778 -9.373,1.499 ; -13.538,2.515 -13.462,2.515 ; -12.344,30.632 1.778,30.632 3.277,32.131 1.448,32.131 0.533,31.217 ; -10.033,6.655 -9.957,6.655 -9.525,6.223 ; -9.703,1.626 -5.588,1.626 -4.928,0.965 ; -9.017,1.118 0.025,1.118 0.584,1.676 ; -6.694,0.864 -6.516,0.686 ; 0.279,1.753 0.279,3.48 ; 0.33,1.422 0.584,1.676 ; 0.33,3.785 0.61,3.785 1.346,3.048 1.346,2.159 1.651,1.854 ; 2.261,1.676 0.584,1.676 ; 9.55,32.004 11.684,32.004 11.709,31.979 ; 9.83,33.071 11.303,33.071 11.862,32.512 11.862,30.531 12.243,30.15 ; 9.881,2.489 9.931,2.438 10.668,2.438 11.557,3.327 11.557,4.394 10.744,5.207 10.744,5.283 ; 10.005,2.87 10.005,4.9 10.414,5.309 ; 11.227,22.504 11.836,23.114 11.836,24.841 11.354,25.324 11.354,25.883 ; 11.303,21.641 11.024,21.361 10.109,21.361 10.236,21.234 12.548,21.234 12.636,21.323 12.636,22.636 12.446,22.826 12.446,25.298 12.065,25.679 12.065,25.781
  Bottom Layer w0.7: -44.196,22.758 -44.196,19.253 -43.993,19.05 -42.164,19.05 -42.113,19.101 -42.113,20.777 -42.545,21.209 -43.866,21.209 -43.891,21.184 -43.891,21.92 -43.764,22.047 -43.764,22.073 -43.053,22.784 -43.053,22.53 -42.875,22.352 ; -30.353,13.741 -30.353,12.675 -30.988,12.04 -30.988,11.024 -30.404,10.439 -24.689,10.439 -24.536,10.592 -24.816,10.592 -25.248,11.024 -29.947,11.024 -30.099,11.176 ; -29.972,9.957 -29.972,9.017 -28.931,7.976 -27.762,7.976 -27.381,8.357 ; -29.362,12.167 -28.423,12.167 -28.346,12.09 ; -29.261,14.148 -29.261,12.624 -28.854,12.217 ; -29.21,8.941 -29.439,9.169 -29.439,9.449 -28.829,10.058 -26.848,10.058 -27.381,9.525 ; -26.238,9.55 -27.381,8.407 -27.381,8.357 ; -24.74,20.574 -24.384,20.574 -24.003,20.955 -24.003,28.397 -23.597,28.804 -22.631,28.804 -22.53,28.905 ; -24.384,10.033 -24.333,10.033 -19.634,5.334 -15.824,5.334 -15.494,5.004 ; -24.105,18.11 -23.927,17.932 -21.869,17.932 -21.844,17.958 -21.844,18.948 -21.962,19.066 -22.851,19.066 ; -23.52,19.253 -23.444,19.329 -23.444,19.837 ; -23.343,8.89 -23.978,9.525 -27.381,9.525 ; -20.142,5.842 -18.161,3.861 -14.503,3.861 -13.716,3.073 ; -18.72,4.75 -15.164,4.75 -15.011,4.597 -15.011,4.343 -15.113,4.242 -18.059,4.242 -18.11,4.293 ; -18.11,8.611 -18.618,8.103 -19.787,8.103 -19.863,8.179 -19.863,8.839 -18.923,8.839 -18.11,9.652 ; -12.044,13.691 -11.739,13.386 -10.516,13.386 ; -6.528,9.119 -6.528,10.82 -6.274,11.074 ; 4.521,20.625 5.893,20.625 6.731,21.463 9.855,21.463 10.693,22.301 11.532,22.301 11.786,22.047 ; 4.979,20.447 5.69,19.736 ; 5.359,20.295 5.588,20.295 5.715,20.168 ; 6.807,33.071 9.525,33.071 9.55,33.045 ; 11.811,26.035 12.065,25.781 ; -27.381,8.357 -27.381,9.525 ; -44.653,18.948 -44.323,18.618 -42.215,18.618 -41.758,19.075 -41.758,21.006 -42.443,21.692 -42.443,22.987 -42.748,23.292 -44.196,23.292 -44.653,22.835 -44.653,18.948 ; -25.222,4.978 -25.222,6.172 -24.892,6.502 -24.13,6.502 -23.546,5.918 -23.546,5.131 -23.851,4.826 -25.07,4.826 -25.222,4.978 ; 2.032,20.396 2.032,21.006 2.184,21.158 3.404,21.158 3.835,20.726 3.835,20.269 3.531,19.964 2.464,19.964 2.032,20.396
  Bottom Layer w0.8: 8.306,32.537 11.151,32.537 11.709,31.979 11.709,29.616 ; 12.065,22.606 12.065,25.781
  Bottom Layer w1: -20.676,28.042 -15.291,28.042 -12.725,30.607 ; -19.99,19.685 -19.99,19.761 -17.958,21.793 ; -19.812,20.422 -19.812,20.472 -18.263,22.022 ; -18.214,25.527 -17.678,25.527 -16.916,24.765 -14.427,24.765 -14.3,24.638 ; -18.136,29.718 -17.323,29.718 -17.272,29.769 ; -16.307,30.15 -17.526,28.931 -21.057,28.931 -20.828,29.159 -20.269,29.159 -21.311,28.118 -22.073,28.118 -22.403,27.788 -22.403,27.737 -23.012,27.127 -23.063,27.127 -23.368,27.432 -23.368,27.635 -22.377,28.626 -20.117,28.626 -19.482,29.261 -14.681,29.261 ; -15.799,30.023 -13.31,30.023 -12.725,30.607 ; -14.757,30.023 -14.808,30.074 -14.808,30.556 -14.757,30.607 -12.725,30.607 ; -8.153,32.055 -6.756,32.055 -6.477,32.334 ; -5.842,32.537 2.134,32.537 2.591,32.08 2.591,31.471 2.438,31.318 2.464,31.318 3.277,32.131 9.322,32.131 9.576,32.385 ; 3.048,20.447 4.979,20.447
  other v2: -11.989,10.541 -12.446,10.592

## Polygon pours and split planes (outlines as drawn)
NetCE2_1 on Top Layer "Top Layer-No Net" (solid, remove dead copper, pour order 1033): -4.918,1.665 4.865,1.575 6.375,3.085 6.375,4.089 6.706,4.42 7.71,4.42 8.153,3.976 8.153,2.819 6.35,1.016 -5.588,1.016 -8.001,3.429 -8.001,4.814 -7.597,5.133 -6.38,5.112
1 on Bottom Layer "Top Layer-No Net" (solid, remove dead copper, pour order 1046): 4.463,13.365 3.498,13.365 3.498,10.479 3.574,10.409 4.895,10.409 5.048,10.548 5.048,11.956 5.835,12.672 5.987,12.811 5.987,12.996 5.987,14.312 5.835,14.45 5.81,14.473 5.657,14.473 4.26,14.473 3.524,13.804 3.498,13.781 3.498,13.365
"NetR2 82.5K_2" on Bottom Layer "Top Layer-No Net" (solid, remove dead copper, pour order 1043): 5.606,6.955 5.606,6.65 6.216,6.65 6.978,7.412 7.588,8.022 7.588,9.393 7.588,11.832 7.359,12.06 7.257,12.162 7.257,12.822 7.257,14.346 7.13,14.473 6.775,14.473 6.648,14.346 6.622,14.321 6.622,14.092 6.622,12.568 6.191,12.137 6.089,12.035 6.089,11.578 6.089,9.622 4.616,8.149 4.616,7.463 4.616,6.726 4.667,6.676 4.692,6.65 5.606,6.65
NetCE2_1 on Bottom Layer "Bottom Layer-No Net" (solid, pour order 1053): -7.91,3.656 -7.404,3.15 -6.516,3.15 -6.008,3.658 -6.008,4.723 -6.49,5.206 -7.584,5.206 -7.91,4.879
2 on Bottom Layer "Top Layer-No Net" (solid, remove dead copper, pour order 1044): 11.659,19.228 11.659,19.634 11.227,19.634 11.125,19.533 11.125,15.697 11.252,15.57 12.852,15.57 13.005,15.723 13.005,19.533 12.903,19.634 11.659,19.634
NetC3_1 on Bottom Layer "Top Layer-No Net" (solid, remove dead copper, pour order 1047): 12.548,11.328 13.03,11.328 13.03,13.894 12.878,14.046 10.338,14.046 9.982,14.402 9.906,14.478 9.398,14.478 9.373,14.478 9.22,14.326 9.195,14.3 9.195,13.31 9.195,12.7 9.322,12.573 9.347,12.548 9.83,12.548 10.744,12.548 11.176,12.116 11.201,12.09 11.201,10.719 11.201,10.592 11.379,10.414 12.878,10.414 12.954,10.49 13.03,10.566 13.03,11.328
NetCE2_1 on Bottom Layer "Top Layer-No Net" (solid, remove dead copper, pour order 1049): 2.692,4.267 2.692,3.251 2.692,3.073 7.798,3.073 8.052,3.327 8.052,6.172 6.909,6.172 6.35,5.613 5.74,5.004 3.429,5.004 2.21,5.004 2.032,4.826 2.032,3.734 2.692,3.073
3 on Bottom Layer "Top Layer-No Net" (solid, remove dead copper, pour order 1051): -5.156,6.782 -5.41,6.782 -5.41,6.121 -5.334,6.045 -3.962,6.045 -3.454,5.537 -3.353,5.436 -3.353,5.131 -2.667,4.445 -2.667,3.023 -2.667,2.362 -2.337,2.032 -1.295,2.032 -0.889,2.438 -0.889,7.689 -1.48,8.28 -3.277,8.28 -3.531,8.026 -3.937,7.62 -4.547,7.62 -5.334,7.62 -5.385,7.569 -5.41,7.544 -5.41,6.782
NetC3_2 on Bottom Layer "Top Layer-No Net" (solid, remove dead copper, pour order 1055): -6.609,10.333 -4.115,12.827 0.025,12.827 0.914,11.938 0.914,10.211 1.016,10.109 2.533,10.105 2.762,10.333 2.762,13.813 4.235,15.286 7.791,15.286 8.223,14.854 8.223,8.364 8.458,8.128 12.725,8.128 12.751,8.153 12.751,9.55 12.725,9.576 10.795,9.576 10.185,10.185 10.185,11.963 10.109,12.04 8.853,12.04 8.654,12.238 8.654,14.702 9.874,15.921 9.874,19.401 9.747,19.528 9.188,19.528 9.086,19.426 9.086,16.759 8.375,16.048 3.854,16.048 3.755,16.048 2.337,14.63 1.245,13.538 -4.799,13.538 -7.493,10.566
4 on Bottom Layer "Top Layer-No Net" (solid, remove dead copper, pour order 1056): -5.131,9.5 -5.385,9.5 -5.385,8.458 -5.309,8.382 -4.267,8.382 -2.438,10.211 -2.438,11.455 -3.429,11.455 -4.775,10.109 -5.182,10.109 -5.232,10.109 -5.385,9.957 -5.385,9.5

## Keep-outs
Keep-Out Layer:
  lines w0.2: -45.614,9.991 -43.114,7.491 -31.364,7.491 -28.514,4.641 -3.414,-1.009 13.386,-1.009 13.386,33.991 -3.414,33.991 -28.364,28.491 -31.364,25.491 -43.114,25.491 -45.614,22.991 -45.614,9.991
  lines w0.7: -39.141,18.186 -39.116,18.212
  lines w1: -39.116,18.212 -39.116,20.65 ; -36.5,15.646 -34.569,15.646 ; -33.033,19.672 -30.734,21.971

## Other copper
Top Layer:
  region net NewNet7: -14.072,25.07 -20.091,25.07 -20.091,21.488 -14.072,21.488
Bottom Layer:
  region net NewNet7: -13.843,24.689 -19.71,24.689 -19.71,21.971 -13.843,21.971

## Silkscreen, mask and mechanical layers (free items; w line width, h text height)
Top Overlay:
  circle w0.254: c8.331,29.718 r1.42
  circle w0.254: c8.407,27.076 r1.433
  circle w0.254: c-42.926,10.986 r1.433
  circle w0.254: c-43.155,19.939 r1.433
  circle w0.254: c8.306,32.537 r1.433
  lines w0.1: 1.245,-0.813 11.354,-0.813 11.354,0.965 1.245,0.965 1.245,-0.787 ; 1.092,23.012 11.405,23.012 11.405,24.968 1.092,24.968 1.092,23.012
  lines w0.6: 3.759,23.292 3.759,24.689 ; 3.835,-0.559 3.835,0.686 ; 6.299,-0.559 6.299,0.686 ; 6.325,23.292 6.325,24.689 ; 8.941,-0.533 8.941,0.711 ; 8.941,23.317 8.941,24.714
  lines w0.7: -4.293,1.473 4.115,1.473 ; 6.68,28.321 9.804,28.321 ; 6.706,31.191 9.855,31.191 9.881,31.217
  lines w1.5: 0.152,29.794 2.896,29.794
  text "V+" at 10.871,33.147 h0.8 r270
  text "V1-" at 10.998,30.734 h0.8 r270
  text "V2-" at 10.998,27.991 h0.8 r270
  text "GND" at -1.727,23.724 h0.8
  text "J1" at 11.735,23.724 h0.8
  text "PWM2" at 6.579,21.59 h0.8
  text "VCC" at 3.556,21.539 h0.8
  text "Bright" at 6.35,20.422 h0.7
  text "L" at -44.882,16.815 h1.5
  text "N" at -45.161,12.395 h1.5
  text "PWM1" at 9.373,1.956 h0.7
  text "Colour" at 8.636,1.118 h0.7
  text "J2" at 11.582,-0.178 h0.8
Bottom Overlay:
  lines w0.4: 4.191,4.912 4.191,8.35
  lines w0.6: 3.734,23.317 3.734,24.714 ; 3.861,-0.61 3.861,0.787 ; 6.223,23.292 6.223,24.689 ; 6.35,-0.635 6.35,0.762 ; 8.89,-0.635 8.89,0.762 ; 8.915,23.292 8.915,24.689
  lines w0.7: -8.484,3.607 -8.484,5.867 ; 0.533,10.439 0.533,12.014 ; 6.553,2.362 7.849,2.362 8.763,3.277 8.763,4.318
  lines w0.8: -6.845,6.388 -5.55,5.093 ; -5.969,8.56 -5.969,10.363 ; -0.508,2.311 -0.508,3.353 ; 10.185,25.984 10.185,30.556
  lines w1: -30.531,15.697 -29.007,15.697
  text "V+" at 5.283,31.674 h0.8 r270
  text "V1-" at 5.486,28.981 h0.8 r270
  text "V2-" at 5.41,26.187 h0.8 r270
  text "L" at -42.824,15.062 h1.5
  text "N" at -42.774,12.827 h1.5

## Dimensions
13.386,-1.009 to -45.614,9.991 on Top Overlay
13.386,33.991 to 13.386,-1.009 on Top Overlay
